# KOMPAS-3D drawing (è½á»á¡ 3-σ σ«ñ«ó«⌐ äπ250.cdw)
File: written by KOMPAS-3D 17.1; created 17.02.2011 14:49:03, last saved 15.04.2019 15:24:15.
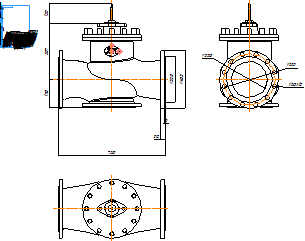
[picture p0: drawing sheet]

Title block, sheet 1: name: Клапан 3-х ходовой Ду250; material: Внимание! Данный продукт является объектом авторского права ООО «Торговый Дом АДЛ». / Запрещается изменение, копирование, распространение / (в том числе путем копирования на другие сайты и ресурсы в Интернете) / или любое иное использование информации и объектов без предварительного / согласия правообладателя (ООО «Торговый Дом АДЛ»).; scale: 1:1; sheets: 1; organisation: ООО "Торговый дом АДЛ"; sheet format: A4; stored path: \\adlc.lan\data\АДЛ_ПКД\3D-модели\ADL production\Клапаны ГРАНРЕГ\Трёхходовой клапан КМ307Ф\KOMPAS 2D\Клапан 3-х ходовой Ду250.cdw

Views: Спереди 1, Проекционный вид 2, Проекционный вид 3
Dimensions and other numbers on the sheet: 320; 405; 190; 387; 135; 730; 3; 28; 250; 355; 30; 1:1; 1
